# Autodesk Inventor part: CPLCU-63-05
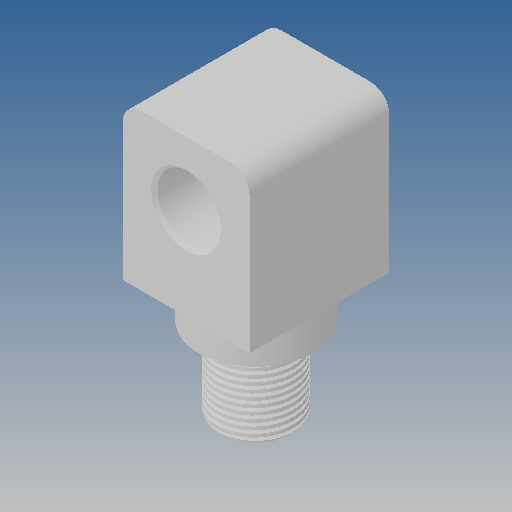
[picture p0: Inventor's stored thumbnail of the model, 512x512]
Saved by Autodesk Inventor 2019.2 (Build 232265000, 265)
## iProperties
Created: 2010-03
Part Number: CPLCU-63-05
Material: Ogólny
Document SubType Name: Modeling
Designer: CADENGINEERING4
Density: 1 g/cm^3
Appearance: Domyślna
Author: CADENGINEERING4
Revision Number: 2LAST_VERSION
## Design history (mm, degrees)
feature "Baza1"
node "Bryła1"
